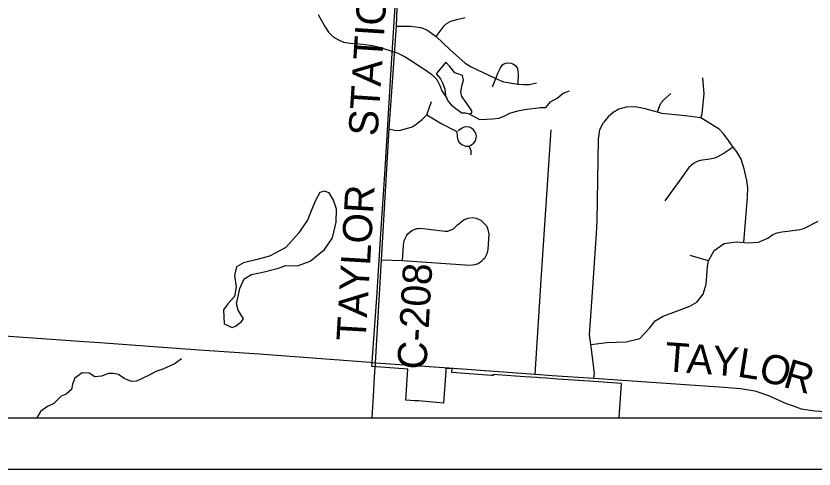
# Model space of a CAD drawing. Extents: x 208586767.6 to 208586821.4, y -134301046.9 to -134301022.9.
# Drawn here: x 208586781.515 to 208586783.069, y -134301030.941 to -134301030.059 of the extents above; entities that cross this region are included whole.
import ezdxf

# ---------------------------------------------------------------- set-up
doc = ezdxf.new("R2010")
doc.units = 0
for name, color, linetype in [('GM_X_Corporation', 7, 'Continuous'), ('GM_X_County_Road', 7, 'Continuous'), ('GM_X_County_Road_Text', 7, 'Continuous'), ('GM_X_Minor_Lake', 7, 'Continuous'), ('GM_X_Minor_River', 7, 'Continuous'), ('GM_X_Township_Road', 7, 'Continuous'), ('SH_Data', 7, 'Continuous')]:
    doc.layers.add(name, color=color, linetype=linetype)

msp = doc.modelspace()

# ---------------------------------------------------------------- linework, layer by layer
at = {"layer": 'GM_X_Corporation'}
for points in [[(208586780.4561, -134301030.8407), (208586784.8283, -134301030.8407), (208586784.8283, -134301027.3051), (208586784.2616, -134301027.2694), (208586783.9036, -134301027.2474), (208586783.5221, -134301027.2233), (208586782.8221, -134301027.178), (208586782.72, -134301027.1729), (208586782.648, -134301027.1691), (208586782.6378, -134301027.1684), (208586782.6086, -134301027.1669), (208586782.1685, -134301027.1422), (208586781.98, -134301027.1295), (208586781.8736, -134301027.1231), (208586781.8549, -134301027.122), (208586781.8329, -134301027.1207), (208586781.7344, -134301027.1148), (208586781.7056, -134301027.1139), (208586781.6677, -134301027.1118), (208586781.2713, -134301027.0897)], [(208586780.416, -134301030.8407), (208586782.689, -134301030.8407), (208586782.6935, -134301030.7743), (208586782.6308, -134301030.7699), (208586782.5689, -134301030.7655), (208586782.5479, -134301030.764), (208586782.5338, -134301030.7631), (208586782.5288, -134301030.7627), (208586782.5055, -134301030.7611), (208586782.4872, -134301030.7598), (208586782.4526, -134301030.7573), (208586782.4442, -134301030.7567), (208586782.444, -134301030.7588), (208586782.4402, -134301030.7585), (208586782.3635, -134301030.7527), (208586782.364, -134301030.7458), (208586782.3517, -134301030.745), (208586782.3515, -134301030.7499), (208586782.3474, -134301030.8123), (208586782.2986, -134301030.8082), (208586782.2915, -134301030.8077), (208586782.2741, -134301030.8064), (208586782.2777, -134301030.7462), (208586782.2341, -134301030.7429), (208586782.2079, -134301030.7413), (208586782.2177, -134301030.6069), (208586782.2255, -134301030.4829), (208586782.2334, -134301030.357), (208586782.2455, -134301030.1628), (208586782.2469, -134301030.1415), (208586782.2611, -134301029.9178)]]:
    msp.add_lwpolyline(points, dxfattribs=at)
at = {"layer": 'GM_X_County_Road'}
msp.add_line((208586781.6784, -134301030.6946), (208586781.7573, -134301030.7005), dxfattribs=at)
for points in [[(208586782.2142, -134301030.7436), (208586782.2147, -134301030.7337), (208586782.2267, -134301030.5332), (208586782.2417, -134301030.2783), (208586782.2556, -134301030.0782), (208586782.2574, -134301030.0255), (208586782.2665, -134301029.8919), (208586782.2694, -134301029.8294), (208586782.276, -134301029.7271)], [(208586780.8016, -134301030.6554), (208586780.8097, -134301030.645), (208586780.8194, -134301030.6387), (208586780.8265, -134301030.6349), (208586780.8332, -134301030.6337), (208586780.8435, -134301030.6332), (208586780.8492, -134301030.6337), (208586780.9247, -134301030.6393), (208586781.0316, -134301030.6472), (208586781.285, -134301030.6663), (208586781.4452, -134301030.6779), (208586781.5477, -134301030.6854), (208586781.6389, -134301030.6916), (208586781.6784, -134301030.6946)], [(208586781.7573, -134301030.7005), (208586781.7741, -134301030.7017), (208586781.8716, -134301030.7085), (208586781.9883, -134301030.7165), (208586782.2048, -134301030.7329)], [(208586782.2048, -134301030.7329), (208586782.2147, -134301030.7337), (208586782.3578, -134301030.7436), (208586782.5255, -134301030.7558), (208586782.5589, -134301030.7583), (208586782.6402, -134301030.764), (208586782.7334, -134301030.7706), (208586782.8938, -134301030.7814), (208586782.9255, -134301030.7836), (208586782.9533, -134301030.7886), (208586782.9798, -134301030.7977), (208586783.0144, -134301030.8131), (208586783.0276, -134301030.8176), (208586783.0436, -134301030.8235), (208586783.0702, -134301030.8273), (208586783.1118, -134301030.8302), (208586783.1629, -134301030.8336), (208586783.2387, -134301030.8384), (208586783.2763, -134301030.8407)], [(208586782.2081, -134301030.8407), (208586782.2108, -134301030.7996), (208586782.2132, -134301030.7614), (208586782.2142, -134301030.7436)]]:
    msp.add_lwpolyline(points, dxfattribs=at)
at = {"layer": 'GM_X_Minor_Lake'}
for points in [[(208586782.3327, -134301030.1712), (208586782.3414, -134301030.1811), (208586782.3459, -134301030.1899), (208586782.3496, -134301030.2013), (208586782.3514, -134301030.2142), (208586782.3559, -134301030.2241), (208586782.3623, -134301030.2314), (208586782.374, -134301030.2409), (208586782.3831, -134301030.247), (208586782.3903, -134301030.2475), (208586782.3979, -134301030.249), (208586782.4021, -134301030.2479), (208586782.4025, -134301030.2434), (208586782.3912, -134301030.227), (208586782.3829, -134301030.2152), (208586782.3807, -134301030.2064), (208586782.3834, -134301030.1928), (208586782.3862, -134301030.1833), (208586782.3843, -134301030.1746), (208586782.3771, -134301030.1719), (208586782.3696, -134301030.1692), (208586782.3598, -134301030.1573), (208586782.3515, -134301030.1486)], [(208586782.3515, -134301030.1486), (208586782.3327, -134301030.1712)], [(208586781.9361, -134301030.6652), (208586781.9422, -134301030.6626), (208586781.9448, -134301030.6603), (208586781.9532, -134301030.6543), (208586781.9578, -134301030.6483), (208586781.9473, -134301030.6315), (208586781.9443, -134301030.619), (208586781.9506, -134301030.5894), (208586781.9594, -134301030.5705), (208586781.9735, -134301030.5622), (208586781.9982, -134301030.5571), (208586782.026, -134301030.5496), (208586782.0401, -134301030.5444), (208586782.0632, -134301030.5449), (208586782.0879, -134301030.536), (208586782.1154, -134301030.5134), (208586782.1311, -134301030.4907), (208586782.1385, -134301030.46), (208586782.139, -134301030.4349), (208586782.1334, -134301030.4175), (208586782.1248, -134301030.403), (208586782.1157, -134301030.3995), (208586782.1062, -134301030.4025), (208586782.0978, -134301030.4176), (208586782.0897, -134301030.4377), (208586782.0831, -134301030.4547), (208586782.0655, -134301030.4808), (208586782.0403, -134301030.5091), (208586782.0083, -134301030.5264), (208586781.9821, -134301030.5334), (208586781.9581, -134301030.539), (208586781.9444, -134301030.5469), (208586781.9405, -134301030.5636), (208586781.9438, -134301030.5863), (208586781.9402, -134301030.6045), (208586781.9272, -134301030.6189), (208586781.9188, -134301030.631), (208586781.9202, -134301030.6579)], [(208586781.9202, -134301030.6579), (208586781.9361, -134301030.6652)]]:
    msp.add_lwpolyline(points, dxfattribs=at)
at = {"layer": 'GM_X_Minor_River'}
for points in [[(208586782.1031, -134301030.056), (208586782.1102, -134301030.0686), (208586782.1162, -134301030.0789), (208586782.1237, -134301030.0899), (208586782.1324, -134301030.0995), (208586782.143, -134301030.1052), (208586782.1528, -134301030.1094), (208586782.1653, -134301030.1114), (208586782.1767, -134301030.1122), (208586782.19, -134301030.1138), (208586782.209, -134301030.1162), (208586782.2222, -134301030.1193), (208586782.2325, -134301030.1224), (208586782.2427, -134301030.1259), (208586782.2582, -134301030.1313), (208586782.2726, -134301030.1379), (208586782.2881, -134301030.1482), (208586782.2983, -134301030.1551), (208586782.3111, -134301030.1627), (208586782.3247, -134301030.1723), (208586782.3345, -134301030.1826)], [(208586782.3345, -134301030.1826), (208586782.3398, -134301030.1937), (208586782.3443, -134301030.2043), (208586782.3535, -134301030.2188)], [(208586782.3972, -134301030.2489), (208586782.4172, -134301030.2601), (208586782.4316, -134301030.2595), (208586782.4426, -134301030.2592), (208586782.4552, -134301030.2573), (208586782.4669, -134301030.2529), (208586782.4765, -134301030.248), (208586782.4917, -134301030.2435), (208586782.5046, -134301030.2406), (208586782.5156, -134301030.2395), (208586782.5262, -134301030.2384), (208586782.5357, -134301030.2366), (208586782.5464, -134301030.2366), (208586782.5555, -134301030.2261), (208586782.5685, -134301030.2185), (208586782.5799, -134301030.2087), (208586782.5925, -134301030.2043)], [(208586781.8374, -134301030.7261), (208586781.8248, -134301030.7355), (208586781.8153, -134301030.74), (208586781.8012, -134301030.746), (208586781.7875, -134301030.7505), (208586781.7746, -134301030.758), (208586781.7609, -134301030.7647), (208586781.7494, -134301030.7696), (208586781.7396, -134301030.7703), (208586781.7259, -134301030.7645), (208586781.7146, -134301030.7569), (208586781.7051, -134301030.7549), (208586781.6949, -134301030.7549), (208586781.6812, -134301030.7597), (208586781.6687, -134301030.7615), (208586781.6577, -134301030.7543), (208586781.644, -134301030.7531), (208586781.6299, -134301030.7636), (208586781.6249, -134301030.7757), (208586781.623, -134301030.7859), (208586781.6127, -134301030.795), (208586781.6031, -134301030.7991), (208586781.589, -134301030.8131), (208586781.5765, -134301030.8191), (208586781.5627, -134301030.8285), (208586781.5555, -134301030.8407)]]:
    msp.add_lwpolyline(points, dxfattribs=at)
at = {"layer": 'GM_X_Township_Road'}
msp.add_line((208586782.8629, -134301030.5354), (208586782.8271, -134301030.525), dxfattribs=at)
for points in [[(208586782.3327, -134301030.0984), (208586782.3486, -134301030.0781), (208586782.3545, -134301030.0729), (208586782.3616, -134301030.0688), (208586782.3735, -134301030.0652), (208586782.3894, -134301030.0615)], [(208586782.2556, -134301030.0782), (208586782.2831, -134301030.0786), (208586782.3033, -134301030.0809), (208586782.3149, -134301030.0856), (208586782.3327, -134301030.0984), (208586782.3598, -134301030.1236), (208586782.3896, -134301030.1502), (208586782.4011, -134301030.1575), (208586782.4489, -134301030.1805), (208586782.4638, -134301030.1866), (208586782.4725, -134301030.1881), (208586782.4917, -134301030.1911), (208586782.5028, -134301030.1922), (208586782.5147, -134301030.1922), (208586782.5281, -134301030.1887)], [(208586782.4424, -134301030.1965), (208586782.4489, -134301030.1805), (208586782.4537, -134301030.1688), (208586782.458, -134301030.1597), (208586782.4628, -134301030.1534), (208586782.4679, -134301030.1504), (208586782.4736, -134301030.15), (208586782.4788, -134301030.1504), (208586782.4824, -134301030.1519), (208586782.4872, -134301030.1552), (208586782.4915, -134301030.1612), (208586782.4926, -134301030.171), (208586782.4917, -134301030.1911)], [(208586782.8483, -134301030.2569), (208586782.8508, -134301030.2492), (208586782.8547, -134301030.2095), (208586782.8518, -134301030.1794)], [(208586782.7641, -134301030.2461), (208586782.7663, -134301030.2379), (208586782.7701, -134301030.2286), (208586782.7768, -134301030.221), (208586782.7899, -134301030.2098)], [(208586782.2417, -134301030.2783), (208586782.2516, -134301030.2812), (208586782.2609, -134301030.2815), (208586782.2752, -134301030.278), (208586782.2863, -134301030.2742), (208586782.2942, -134301030.2693), (208586782.3055, -134301030.2601), (208586782.3146, -134301030.2514), (208586782.324, -134301030.2249)], [(208586782.932, -134301030.4994), (208586782.9389, -134301030.4117), (208586782.9394, -134301030.3934), (208586782.9379, -134301030.3787), (208586782.9324, -134301030.3562), (208586782.9265, -134301030.3374), (208586782.9181, -134301030.323), (208586782.9114, -134301030.3139), (208586782.899, -134301030.2966), (208586782.8921, -134301030.2878), (208586782.8837, -134301030.2791), (208586782.8483, -134301030.2569), (208586782.8179, -134301030.2529), (208586782.7724, -134301030.2482), (208586782.7641, -134301030.2461), (208586782.7401, -134301030.2393), (208586782.7305, -134301030.2374), (208586782.7195, -134301030.2358), (208586782.703, -134301030.2361), (208586782.6888, -134301030.2404), (208586782.6775, -134301030.2463), (208586782.6678, -134301030.2551), (208586782.6586, -134301030.2662)], [(208586782.3146, -134301030.2514), (208586782.3442, -134301030.2689), (208586782.3668, -134301030.2802), (208586782.3734, -134301030.2835), (208586782.3741, -134301030.2942), (208586782.3759, -134301030.3021), (208586782.3791, -134301030.3066), (208586782.384, -134301030.3098), (208586782.3905, -134301030.3122), (208586782.3972, -134301030.312), (208586782.4018, -134301030.3094), (208586782.4063, -134301030.3055), (208586782.4095, -134301030.3015), (208586782.4108, -134301030.296), (208586782.4112, -134301030.292), (208586782.4101, -134301030.2865), (208586782.4059, -134301030.2804), (208586782.4016, -134301030.277), (208586782.3976, -134301030.2749), (208586782.3929, -134301030.2743), (208586782.3874, -134301030.2751), (208586782.3824, -134301030.2774), (208586782.3759, -134301030.2822)], [(208586782.6402, -134301030.764), (208586782.641, -134301030.7548), (208586782.6368, -134301030.7177), (208586782.6343, -134301030.6982), (208586782.6315, -134301030.6787), (208586782.6358, -134301030.6158), (208586782.6451, -134301030.4822), (208586782.6461, -134301030.4575), (208586782.6488, -134301030.2985), (208586782.6518, -134301030.2796), (208586782.6586, -134301030.2662)], [(208586782.5255, -134301030.7558), (208586782.5377, -134301030.5627), (208586782.5569, -134301030.2804)], [(208586782.4012, -134301030.3293), (208586782.4008, -134301030.321), (208586782.3972, -134301030.312)], [(208586782.9114, -134301030.3139), (208586782.8936, -134301030.326), (208586782.8822, -134301030.332), (208586782.8753, -134301030.3352), (208586782.8656, -134301030.3377), (208586782.8466, -134301030.3401), (208586782.8409, -134301030.3421), (208586782.8339, -134301030.3458), (208586782.825, -134301030.3537), (208586782.8072, -134301030.3785), (208586782.778, -134301030.4187)], [(208586782.2677, -134301030.535), (208586782.2697, -134301030.5058), (208586782.2701, -134301030.5001), (208586782.2709, -134301030.4962), (208586782.2725, -134301030.4917), (208586782.2751, -134301030.4869), (208586782.2779, -134301030.4831), (208586782.2816, -134301030.4795), (208586782.2858, -134301030.4765), (208586782.2905, -134301030.4742), (208586782.295, -134301030.4727), (208586782.2983, -134301030.4721), (208586782.302, -134301030.4718), (208586782.3507, -134301030.4779), (208586782.3559, -134301030.4773), (208586782.3665, -134301030.4731), (208586782.3748, -134301030.4651), (208586782.3876, -134301030.4548), (208586782.3954, -134301030.452), (208586782.4037, -134301030.451), (208586782.4109, -134301030.4526), (208586782.4198, -134301030.4565), (208586782.426, -134301030.4623), (208586782.4308, -134301030.4671), (208586782.4335, -134301030.4744), (208586782.4358, -134301030.4835), (208586782.4333, -134301030.5134), (208586782.4314, -134301030.5216), (208586782.427, -134301030.5305), (208586782.4244, -134301030.533), (208586782.4217, -134301030.5352)], [(208586782.981, -134301030.4896), (208586782.9886, -134301030.4844), (208586782.9966, -134301030.4811), (208586783.0059, -134301030.4788), (208586783.0174, -134301030.4776), (208586783.041, -134301030.4745), (208586783.049, -134301030.4725), (208586783.0763, -134301030.4583)], [(208586782.6343, -134301030.6982), (208586782.6654, -134301030.6941), (208586782.7027, -134301030.693), (208586782.7296, -134301030.6867), (208586782.7485, -134301030.6666), (208586782.7592, -134301030.6522), (208586782.7746, -134301030.643), (208586782.8265, -134301030.6238), (208586782.8405, -134301030.6158), (208586782.853, -134301030.6002), (208586782.8585, -134301030.581), (208586782.8609, -134301030.5466), (208586782.8629, -134301030.5354), (208586782.8744, -134301030.515), (208586782.8936, -134301030.5017), (208586782.9168, -134301030.4983), (208586782.932, -134301030.4994), (208586782.9405, -134301030.5001), (208586782.9602, -134301030.4987), (208586782.9784, -134301030.4913), (208586782.981, -134301030.4896)], [(208586782.2267, -134301030.5332), (208586782.2677, -134301030.535), (208586782.3982, -134301030.5435), (208586782.4086, -134301030.5423), (208586782.415, -134301030.5406), (208586782.4217, -134301030.5352)]]:
    msp.add_lwpolyline(points, dxfattribs=at)
at = {"layer": 'SH_Data'}
for p, q in [((208586778.0283, -134301030.8407), (208586784.8283, -134301030.8407)), ((208586777.9283, -134301030.9407), (208586784.9283, -134301030.9407))]:
    msp.add_line(p, q, dxfattribs=at)

# ---------------------------------------------------------------- texts
at = {"layer": 'GM_X_County_Road_Text'}
for s, height, rotation, p in [('STATION', 0.05682, 86.3005, (208586782.2187, -134301030.2936)), ('TAYLOR', 0.05682, 86.6237, (208586782.1954, -134301030.6928)), ('C-208', 0.05682, 86.6978, (208586782.3137, -134301030.7481)), ('T', 0.0568, 355.8695, (208586782.7768, -134301030.7501)), ('A', 0.0568, 355.8692, (208586782.8192, -134301030.7532)), ('Y', 0.0568, 355.5477, (208586782.869, -134301030.7568)), ('L', 0.0568, 351.0104, (208586782.9176, -134301030.7605)), ('O', 0.0568, 344.4599, (208586782.9579, -134301030.7668)), ('R', 0.0568, 343.8798, (208586783.006, -134301030.7801))]:
    msp.add_text(s, height=height, rotation=rotation, dxfattribs=at).set_placement(p)

doc.saveas('drawing.dxf')
